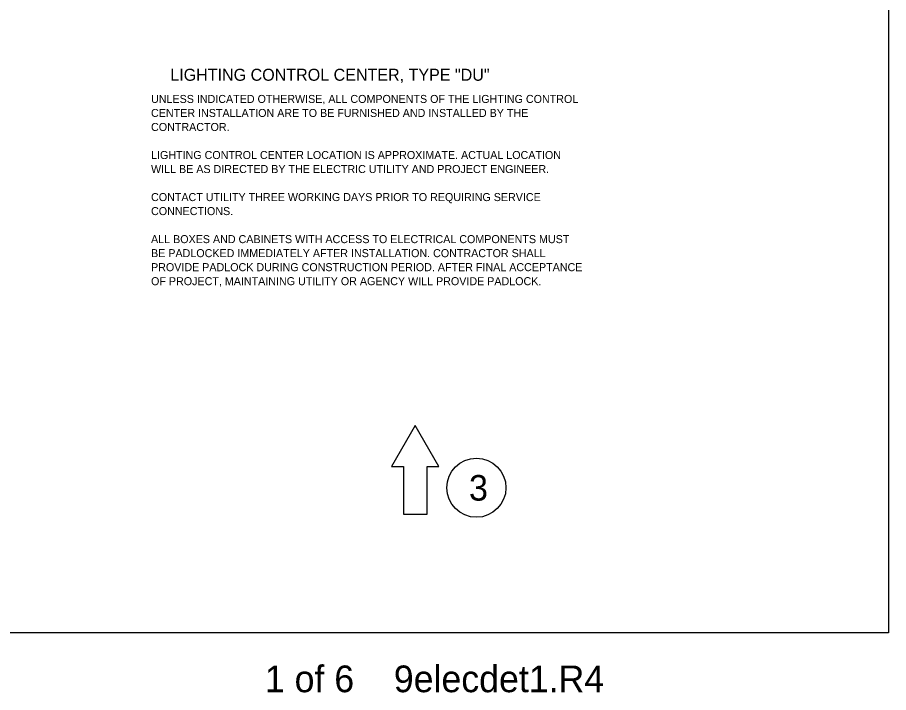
# Model space of a CAD drawing. Extents: x 100006 to 118406, y 96592 to 102182.
# Drawn here: x 101900 to 103206, y 99797 to 100808 of the extents above; entities that cross this region are included whole.
import ezdxf

# ---------------------------------------------------------------- set-up
doc = ezdxf.new("R2010")
doc.units = 0
for name, color, linetype in [('Default', 7, 'Continuous'), ('Level 7', 7, 'Continuous'), ('Level 9', 7, 'Continuous'), ('RD Standard Plans Active', 7, 'Continuous')]:
    doc.layers.add(name, color=color, linetype=linetype)

msp = doc.modelspace()

# ---------------------------------------------------------------- linework, layer by layer
at = {"layer": 'Default'}
msp.add_lwpolyline([(100006.1, 102085.7), (103205.8, 102085.7), (103205.8, 99886.1), (100006.1, 99886.1)], close=True, dxfattribs=at)
at = {"layer": 'Level 9'}
msp.add_lwpolyline([(102496.5, 100196.4), (102461, 100135), (102478.8, 100135), (102478.8, 100064), (102514.2, 100064), (102514.2, 100135), (102532, 100135)], close=True, dxfattribs=at)
msp.add_circle((102588.2, 100103.3), 44.2, dxfattribs=at)

# ---------------------------------------------------------------- texts
at = {"layer": 'Level 7'}
for s, height, p in [('LIGHTING CONTROL CENTER, TYPE "DU"', 18, (102129.4, 100713)), ('UNLESS INDICATED OTHERWISE, ALL COMPONENTS OF THE LIGHTING CONTROL', 12, (102100.6, 100679.8)), ('CENTER INSTALLATION ARE TO BE FURNISHED AND INSTALLED BY THE', 12, (102100.6, 100658.8)), ('CONTRACTOR.', 12, (102100.6, 100637.8)), ('LIGHTING CONTROL CENTER LOCATION IS APPROXIMATE. ACTUAL LOCATION', 12, (102100.6, 100595.8)), ('WILL BE AS DIRECTED BY THE ELECTRIC UTILITY AND PROJECT ENGINEER.', 12, (102100.6, 100574.8)), ('CONTACT UTILITY THREE WORKING DAYS PRIOR TO REQUIRING SERVICE', 12, (102100.6, 100532.8)), ('CONNECTIONS.', 12, (102100.6, 100511.8)), ('ALL BOXES AND CABINETS WITH ACCESS TO ELECTRICAL COMPONENTS MUST', 12, (102100.6, 100469.8)), ('BE PADLOCKED IMMEDIATELY AFTER INSTALLATION. CONTRACTOR SHALL', 12, (102100.6, 100448.8)), ('PROVIDE PADLOCK DURING CONSTRUCTION PERIOD. AFTER FINAL ACCEPTANCE', 12, (102100.6, 100427.8)), ('OF PROJECT, MAINTAINING UTILITY OR AGENCY WILL PROVIDE PADLOCK.', 12, (102100.6, 100406.8))]:
    msp.add_text(s, height=height, dxfattribs=at).set_placement(p)
at = {"layer": 'Level 9'}
msp.add_text('3', height=38.3, dxfattribs=at).set_placement((102577, 100084.1))
at = {"layer": 'RD Standard Plans Active'}
msp.add_text('     1 of 6    9elecdet1.R4', height=40, dxfattribs=at).set_placement((102196.8, 99797.1))

doc.saveas('drawing.dxf')
